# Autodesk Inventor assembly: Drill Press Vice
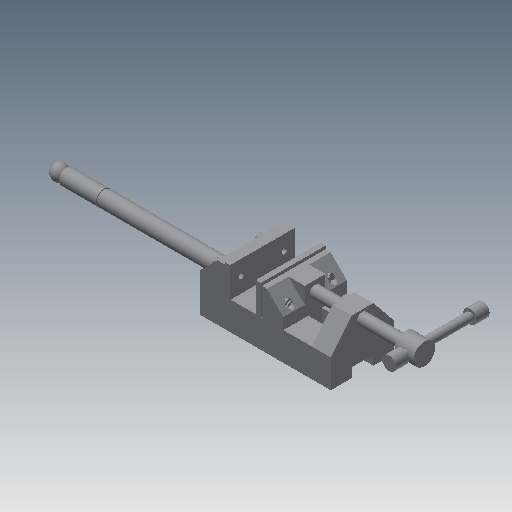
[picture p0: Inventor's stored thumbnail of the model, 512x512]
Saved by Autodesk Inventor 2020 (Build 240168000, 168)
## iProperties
Created: 2009-05
Part Number: Drill Press Vice
Document SubType Name: Assembly
Designer: Sham
Author: Sham
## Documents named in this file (9)
- D:\Autodesk Inventor_2020\Resources\Resources\Inventor_2019_tut\Inventor_2019_tut\c12_Inv_2019_tut\c12_Inv_tut_2019\c12_tut03_inv\Drill Press Vice.iam
- D:\Autodesk Inventor_2020\Resources\Resources\Inventor_2019_tut\Inventor_2019_tut\c12_Inv_2019_tut\c12_Inv_tut_2019\c12_tut03_inv\Base.ipt
- D:\Autodesk Inventor_2020\Resources\Resources\Inventor_2019_tut\Inventor_2019_tut\c12_Inv_2019_tut\c12_Inv_tut_2019\c12_tut03_inv\Safety Handle.ipt
- D:\Autodesk Inventor_2020\Resources\Resources\Inventor_2019_tut\Inventor_2019_tut\c12_Inv_2019_tut\c12_Inv_tut_2019\c12_tut03_inv\Jaw Face.ipt
- D:\Autodesk Inventor_2020\Resources\Resources\Inventor_2019_tut\Inventor_2019_tut\c12_Inv_2019_tut\c12_Inv_tut_2019\c12_tut03_inv\Movable Jaw.ipt
- D:\Autodesk Inventor_2020\Resources\Resources\Inventor_2019_tut\Inventor_2019_tut\c12_Inv_2019_tut\c12_Inv_tut_2019\c12_tut03_inv\Cap Screw.ipt
- D:\Autodesk Inventor_2020\Resources\Resources\Inventor_2019_tut\Inventor_2019_tut\c12_Inv_2019_tut\c12_Inv_tut_2019\c12_tut03_inv\Clamp Screw Handle.ipt
- D:\Autodesk Inventor_2020\Resources\Resources\Inventor_2019_tut\Inventor_2019_tut\c12_Inv_2019_tut\c12_Inv_tut_2019\c12_tut03_inv\Clamp Screw.ipt
- D:\Autodesk Inventor_2020\Resources\Resources\Inventor_2019_tut\Inventor_2019_tut\c12_Inv_2019_tut\c12_Inv_tut_2019\c12_tut03_inv\Handle Stop.ipt
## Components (13 placed, 8 different names)
1. Base:1 — Mate:2, Mate:3, Mate:7, Insert:10, Insert:11, Insert:12, Insert:13
2. Safety Handle:1
3. Jaw Face:1 — Insert:8, Insert:9, Mate:7
4. Jaw Face:2 — Insert:10, Insert:11
5. Movable Jaw:1 — Mate:2, Mate:3, Insert:2, Insert:3, Insert:4, Insert:8, Insert:9
6. Cap Screw:1 — Insert:2
7. Cap Screw:2 — Insert:3
8. Cap Screw:3 — Insert:13
9. Cap Screw:4 — Insert:12
10. Clamp Screw:1 — Insert:4, Mate:6, Rotation/Translation:2
11. Clamp Screw Handle:1 — Mate:6, Insert:5, Insert:6, Rotation/Translation:2
12. Handle Stop:1 — Insert:6, Mate:8
13. Handle Stop:2 — Insert:5
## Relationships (17: Insert 11, Mate 5, RelateRotateTranslate 1)
- Mate:2: Base:1 ↔ Movable Jaw:1
- Mate:3: Base:1 ↔ Movable Jaw:1
- Insert:2: Movable Jaw:1 ↔ Cap Screw:1
- Insert:3: Movable Jaw:1 ↔ Cap Screw:2
- Insert:4: Movable Jaw:1 ↔ Clamp Screw:1
- Mate:6: Clamp Screw:1 ↔ Clamp Screw Handle:1
- Insert:5: Clamp Screw Handle:1 ↔ Handle Stop:2
- Insert:6: Clamp Screw Handle:1 ↔ Handle Stop:1
- Insert:8: Jaw Face:1 ↔ Movable Jaw:1
- Insert:9: Jaw Face:1 ↔ Movable Jaw:1
- Mate:7: Base:1 ↔ Jaw Face:1
- Rotation/Translation:2 [RelateRotateTranslate]: Clamp Screw:1 ↔ Clamp Screw Handle:1
- Mate:8: Handle Stop:1
- Insert:10: Base:1 ↔ Jaw Face:2
- Insert:11: Base:1 ↔ Jaw Face:2
- Insert:12: Base:1 ↔ Cap Screw:4
- Insert:13: Base:1 ↔ Cap Screw:3
